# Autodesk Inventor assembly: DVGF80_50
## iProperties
Created: 2010-04
Part Number: DVGF80_50
Document SubType Name: Assembly
Designer: TB
Mass: 1911.83 g
Surface Area: 2444.85 cm^2
Volume: 1911.83 cm^3
Density: 1 g/cm^3
Description: KM DVGF 80/50 - 100 mm
Slaglengde: 100.000 mm
Author: TB
